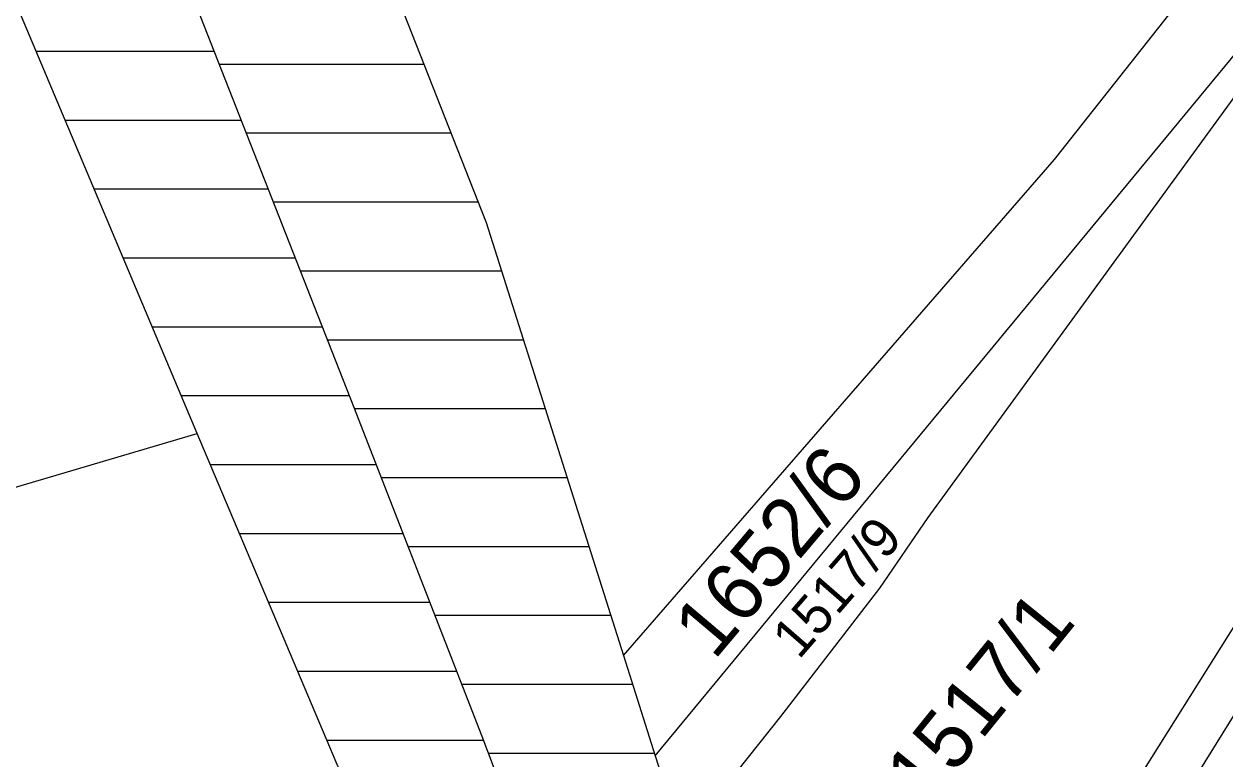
# Model space of a CAD drawing. Extents: x -553916 to -552953, y -1067470 to -1066637.
# Drawn here: x -553532.46 to -553497.58, y -1066968.6 to -1066947.27 of the extents above; entities that cross this region are included whole.
import ezdxf

# ---------------------------------------------------------------- set-up
doc = ezdxf.new("R2010")
doc.units = 0
for name, color, linetype in [('Hranice parcel', 7, 'Continuous'), ('Kolej', 7, 'Continuous'), ('Parcelní čísla', 7, 'Continuous'), ('Vrstva 1', 7, 'Continuous')]:
    doc.layers.add(name, color=color, linetype=linetype)

msp = doc.modelspace()

# ---------------------------------------------------------------- linework, layer by layer
at = {"layer": 'Hranice parcel'}
for p, q in [((-553514.13, -1066968.51), (-553489.9, -1066939.2)), ((-553486.47, -1066947.45), (-553499.93, -1066968.9)), ((-553545.85, -1066964.59), (-553527.43, -1066959.15))]:
    msp.add_line(p, q, dxfattribs=at)
for points in [[(-553515.05, -1066965.6), (-553502.53, -1066951.2), (-553486.22, -1066930.56), (-553479.63, -1066908.8), (-553477.16, -1066903.7)], [(-553489.9, -1066939.2), (-553506.21, -1066961.59), (-553507.62, -1066963.64), (-553510.49, -1066967.37), (-553513.35, -1066970.96)], [(-553481.25, -1066991.64), (-553501.02, -1066983.66), (-553503.13, -1066976.7), (-553485.37, -1066948.09)]]:
    msp.add_lwpolyline(points, dxfattribs=at)
at = {"layer": 'Kolej'}
msp.add_lwpolyline([(-553503.324, -1067065.808), (-553502.678, -1067054.027), (-553502.762, -1067041.504), (-553503.626, -1067029.057), (-553504.756, -1067019.974), (-553506.183, -1067011.388), (-553508.328, -1067001.388), (-553510.948, -1066991.622), (-553512.921, -1066985.291), (-553515.647, -1066977.347), (-553517.422, -1066972.53), (-553519.157, -1066967.95), (-553522.886, -1066958.375), (-553529.101, -1066942.549), (-553538.686, -1066918.107), (-553542.908, -1066907.329), (-553546.692, -1066897.676), (-553555.025, -1066876.441), (-553564.644, -1066851.894), (-553574.241, -1066827.427), (-553583.19, -1066804.618)], dxfattribs=at)
at = {"layer": 'Vrstva 1'}
for p, q in [((-553527.43, -1066959.15), (-553535.26, -1066940.6)), ((-553532.114, -1066948.052), (-553526.94, -1066948.052)), ((-553526.792, -1066948.429), (-553520.852, -1066948.429)), ((-553531.27, -1066950.052), (-553526.155, -1066950.052)), ((-553526.006, -1066950.429), (-553520.065, -1066950.429)), ((-553530.426, -1066952.052), (-553525.369, -1066952.052)), ((-553525.221, -1066952.429), (-553519.277, -1066952.429)), ((-553529.582, -1066954.052), (-553524.584, -1066954.052)), ((-553524.436, -1066954.429), (-553518.596, -1066954.429)), ((-553528.738, -1066956.052), (-553523.798, -1066956.052)), ((-553523.65, -1066956.429), (-553517.961, -1066956.429)), ((-553527.893, -1066958.052), (-553523.013, -1066958.052)), ((-553522.865, -1066958.429), (-553517.326, -1066958.429)), ((-553527.049, -1066960.052), (-553522.233, -1066960.052)), ((-553522.086, -1066960.429), (-553516.691, -1066960.429)), ((-553526.204, -1066962.052), (-553521.454, -1066962.052)), ((-553521.307, -1066962.429), (-553516.057, -1066962.429)), ((-553525.359, -1066964.052), (-553520.675, -1066964.052)), ((-553520.528, -1066964.429), (-553515.422, -1066964.429)), ((-553515.05, -1066965.6), (-553514.13, -1066968.51)), ((-553524.514, -1066966.052), (-553519.896, -1066966.052)), ((-553519.749, -1066966.429), (-553514.788, -1066966.429)), ((-553523.67, -1066968.052), (-553519.118, -1066968.052)), ((-553518.976, -1066968.429), (-553514.156, -1066968.429)), ((-553514.13, -1066968.51), (-553513.35, -1066970.96))]:
    msp.add_line(p, q, dxfattribs=at)
for points in [[(-553537.18, -1066906.98), (-553519.04, -1066953.03), (-553515.05, -1066965.6)], [(-553521.68, -1066973.05), (-553522.23, -1066971.46), (-553527.43, -1066959.15)]]:
    msp.add_lwpolyline(points, dxfattribs=at)

# ---------------------------------------------------------------- texts
at = {"layer": 'Parcelní čísla'}
for s, height, rotation, p in [('1652/6', 1.7, 49.8322, (-553512.418, -1066965.759)), ('1517/9', 1.14, 49, (-553509.959, -1066965.739)), ('1517/1', 1.7, 51, (-553506.254, -1066970.044))]:
    msp.add_text(s, height=height, rotation=rotation, dxfattribs=at).set_placement(p)

doc.saveas('drawing.dxf')
